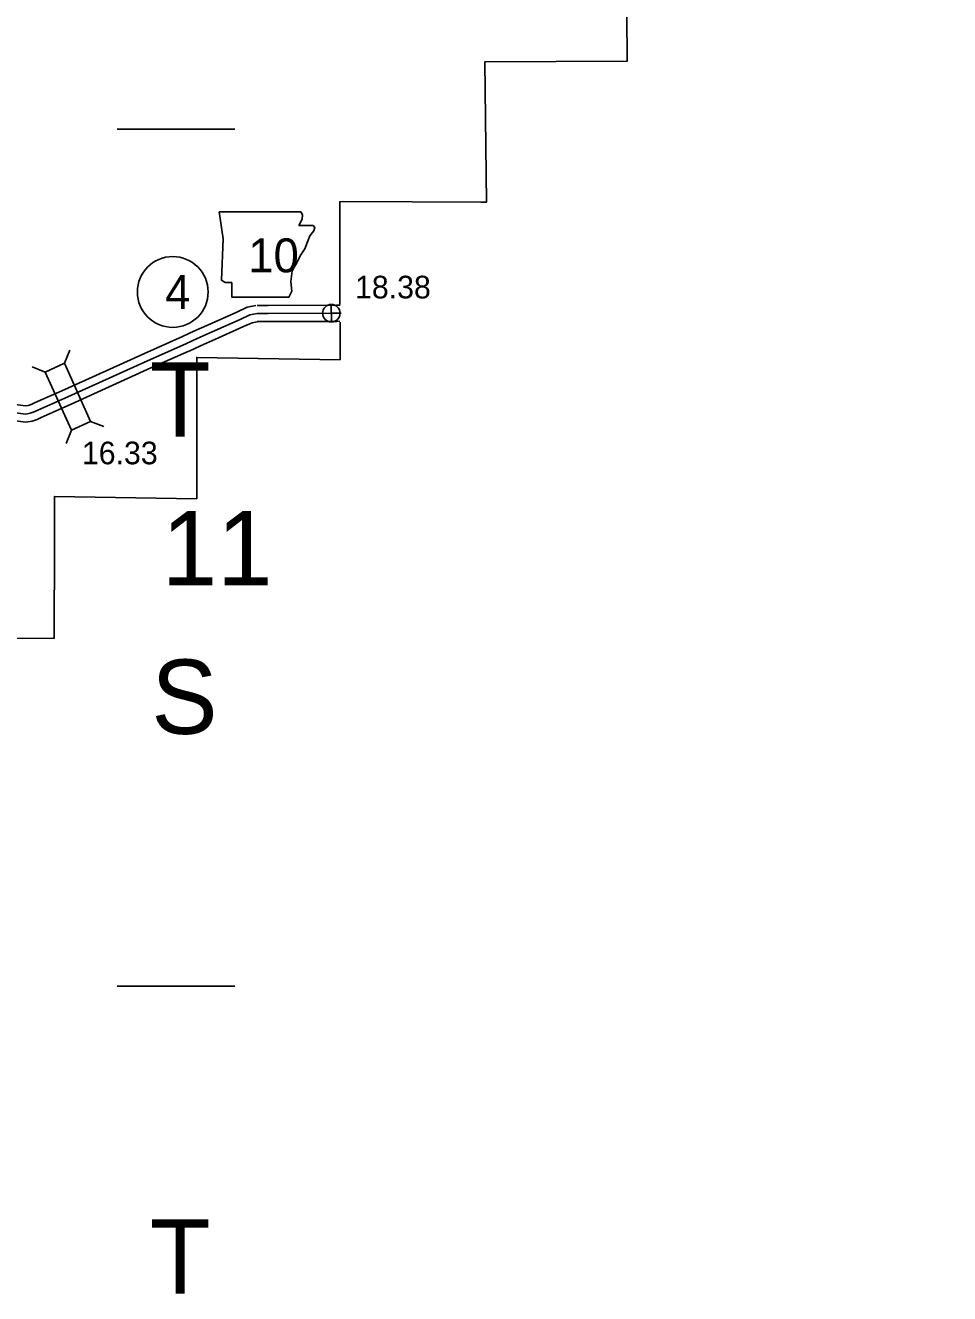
# Model space of a CAD drawing. Extents: x 31699 to 244310, y -8841 to 11474.
# Drawn here: x 96546 to 97695, y -219 to 1358 of the extents above; entities that cross this region are included whole.
import ezdxf

# ---------------------------------------------------------------- set-up
doc = ezdxf.new("R2010")
doc.units = 0
for name, color, linetype in [('B_Logo', 7, 'Continuous'), ('Default', 7, 'Continuous'), ('G-ANNO-TEXT', 7, 'Continuous'), ('Level 21', 7, 'Continuous'), ('R_Border', 7, 'Continuous'), ('R_Border Notes', 7, 'Continuous'), ('R_Logo', 7, 'Continuous'), ('R_XS_EARTHWORK_STAGE1', 7, 'Continuous'), ('R_XS_EARTHWORK_STAGE2', 7, 'Continuous'), ('S_WALL', 7, 'Continuous'), ('S_WALL_ANNOT', 7, 'Continuous')]:
    doc.layers.add(name, color=color, linetype=linetype)

msp = doc.modelspace()

# ---------------------------------------------------------------- linework, layer by layer
at = {"layer": 'B_Logo'}
for points in [[(96781.8, 978.2), (96812.9, 992.1), (96824.7, 997.5), (96834, 999.4)], [(96938.3, 999.9), (96932.6, 999.6), (96847.8, 999.4), (96834, 999.4)], [(96745.1, 961.6), (96759.2, 968.1), (96781.8, 978.2)], [(96464.3, 884.9), (96546.1, 874.4), (96551.7, 875.3), (96556.6, 877), (96561.1, 879), (96598.7, 895.9), (96697.7, 940.7), (96745.1, 961.6)]]:
    msp.add_lwpolyline(points, dxfattribs=at)
at = {"layer": 'Default'}
for p, q in [((96806.3, 1228.6), (96660, 1228.6)), ((96806.3, 163.1), (96660, 163.1))]:
    msp.add_line(p, q, dxfattribs=at)
at = {"layer": 'G-ANNO-TEXT'}
msp.add_lwpolyline([(96786.6, 1125.8), (96791.7, 1092), (96789.5, 1040.6), (96794, 1037.8), (96802.4, 1037.8), (96802.4, 1019.8), (96873.5, 1019.8), (96876.9, 1027.1), (96875.7, 1039), (96877.4, 1052.5), (96883.6, 1063.2), (96887.6, 1071.1), (96893.2, 1079.6), (96896.6, 1088.6), (96899.4, 1095.9), (96904.5, 1102.1), (96905.6, 1106.1), (96903.4, 1108.9), (96885.9, 1108.9), (96889.8, 1116.8), (96890.4, 1121.9), (96888.1, 1125.8)], close=True, dxfattribs=at)
at = {"layer": 'Level 21'}
for p, q in [((96926.4, 988.9), (96925.9, 1010.6)), ((96915.3, 999.5), (96937, 1000))]:
    msp.add_line(p, q, dxfattribs=at)
msp.add_circle((96926.1, 999.7), 10.9, dxfattribs=at)
at = {"layer": 'R_Border Notes'}
msp.add_circle((96729, 1026.1), 44, dxfattribs=at)
at = {"layer": 'R_Logo'}
for points in [[(97695, 1666.8), (97645.5, 1669.2), (97468.7, 1665.5), (97469.8, 1488.7), (97292.6, 1488.8), (97293.8, 1312.9), (97117.2, 1312.4), (97119, 1137.7), (97112.1, 1137.6), (96941.5, 1138.5), (96936.7, 1138.3), (96936.9, 1010.9)], [(96937, 988.7), (96937, 941.8), (96758.8, 944.7), (96759.1, 768.8)], [(96759.1, 768.8), (96581.9, 772), (96581.8, 715.7)], [(96581.8, 715.7), (96581.4, 595.5), (96401.4, 596.4), (96405.1, 419.4), (96326, 419.9)]]:
    msp.add_lwpolyline(points, dxfattribs=at)
at = {"layer": 'R_XS_EARTHWORK_STAGE1'}
for p, q in [((96594.5, 937.4), (96600.8, 953.9)), ((96570.4, 926.6), (96554, 932.9)), ((96602.9, 854.4), (96596.6, 837.9)), ((96626.9, 865.2), (96643.4, 858.9))]:
    msp.add_line(p, q, dxfattribs=at)
msp.add_lwpolyline([(96570.4, 926.6), (96602.9, 854.4), (96626.9, 865.2), (96594.5, 937.4)], close=True, dxfattribs=at)
at = {"layer": 'R_XS_EARTHWORK_STAGE2'}
for points in [[(95772.4, 1041.7), (95866.2, 1024.5), (95990.2, 998.1), (96035.1, 988.8), (96070.4, 987.1), (96176.8, 950.8), (96242.6, 921), (96255.8, 915.5), (96257.3, 915.2), (96260.6, 915.1), (96362.9, 922.6), (96397.9, 906.9), (96408.9, 903.1), (96465.7, 894.9), (96546, 884.5), (96549.3, 885), (96552.9, 886.3), (96557, 888.1), (96594.6, 905), (96693.7, 949.8), (96741, 970.8)], [(95765.5, 1022.6), (95862.3, 1004.9), (95986.1, 978.5), (96032.6, 968.9), (96066.7, 967.2), (96169.4, 932.2), (96234.6, 902.7), (96249.8, 896.4), (96254.8, 895.2), (96261, 895), (96359.3, 902.3), (96390.5, 888.3), (96404.2, 883.5), (96463, 875), (96546.2, 864.4), (96554.1, 865.5), (96560.4, 867.7), (96565.2, 869.9), (96602.8, 886.8), (96701.8, 931.6), (96749.1, 952.5)], [(96777.8, 987.4), (96808.7, 1001.2), (96821.6, 1007.1), (96832.1, 1009.2)], [(96834, 1009.4), (96847.7, 1009.4), (96932.4, 1009.6), (96937.2, 1009.8)], [(96740.9, 970.7), (96755.1, 977.2), (96777.8, 987.4)], [(96785.9, 969.1), (96817, 983), (96827.8, 987.9), (96836, 989.6)], [(96834.1, 989.4), (96847.8, 989.4), (96932.8, 989.6), (96936.8, 989.8)], [(96749.3, 952.5), (96763.4, 959), (96785.9, 969.1)]]:
    msp.add_lwpolyline(points, dxfattribs=at)

# ---------------------------------------------------------------- texts
at = {"layer": 'G-ANNO-TEXT'}
msp.add_text('10', height=42.24, dxfattribs=at).set_placement((96822.9, 1050.5))
at = {"layer": 'R_Border'}
for s, p in [('T', (96700.5, 846.3)), ('11', (96715.4, 661.5)), ('S', (96702.3, 476.7)), ('T', (96700.5, -219.2))]:
    msp.add_text(s, height=92.4, dxfattribs=at).set_placement(p)
at = {"layer": 'R_Border Notes'}
msp.add_text('4', height=42.2, dxfattribs=at).set_placement((96719.5, 1005))
at = {"layer": 'S_WALL'}
msp.add_text('16.33', height=28.16, dxfattribs=at).set_placement((96616, 811.9))
at = {"layer": 'S_WALL_ANNOT'}
msp.add_text('18.38', height=28.16, dxfattribs=at).set_placement((96955.6, 1018.1))

doc.saveas('drawing.dxf')
